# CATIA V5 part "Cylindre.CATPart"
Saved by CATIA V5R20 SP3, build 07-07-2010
Part number: Cylindre
Bounding box of the stored display mesh (mm): x -34.49 to 34.49, y -34.387 to 34.387, z -147 to -6
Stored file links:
  F:\Travaux\Modélisations\CFAO_2011\MMS\MMS_GR1\AA_OK\bmadec\Catia\Cylindre.CATPart
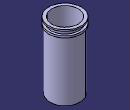
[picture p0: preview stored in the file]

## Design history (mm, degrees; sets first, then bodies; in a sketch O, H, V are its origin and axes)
Body1 (main body)
  Sketch1 on yz-plane, origin (0, 0, 0), H (0, 1, 0), V (0, 0, 1)
    line L1 (34.5, -6) -> (34.5, -21)
    line L2 (34.5, -21) -> (31.5, -21)
    line L3 (31.5, -21) -> (31.5, -147)
    line L4 (31.5, -147) -> (24.75, -147)
    line L5 (24.75, -147) -> (24.75, -123)
    line L6 (24.75, -123) -> (28, -123)
    line L7 (28, -123) -> (28, -6)
    line L8 (28, -6) -> (34.5, -6)
    distance L1 V = 34.5
    distance L3 V = 31.5
    distance L5 V = 24.75
    length L5 = 24
    length L1 = 15
    distance L8 L4 = 141
    distance L8 H = 6
    distance V L7 = 28
    vertical: L1 V, L3 V, L5 V, L7 V
    horizontal: L2 H, L4 H, L6 H, L8 H
  Shaft1: profile Sketch1, axis Sketch1.V, angle 360
  Sketch2 on yz-plane, origin (0, 0, 0), H (0, 1, 0), V (0, 0, 1)
    line L1 (35.9718, -9) -> (30, -9)
    line L2 (30, -9) -> (30, -17)
    line L3 (30, -17) -> (35.9718, -17)
    line L4 (35.9718, -17) -> (35.9718, -9)
    distance L1 H = 9
    length L2 = 8
    distance L2 V = 30
    horizontal: L1 H, L3 H
    vertical: L2 V, L4 V
  Groove1: profile Sketch2, axis Sketch2.V, angle 360
  Sketch3 on yz-plane, origin (0, 0, 0), H (0, 1, 0), V (0, 0, 1)
    line L1 (16.9243, -127) -> (29, -127)
    line L2 (29, -127) -> (29, -142)
    line L3 (29, -142) -> (16.9243, -142)
    line L4 (16.9243, -142) -> (16.9243, -127)
    reference projected line E1 (-31.5, -147) -> (31.5, -147) from edge [face of Shaft1 from Sketch1.L4 | face of Shaft1 from Sketch1.L3]
    reference projected line E2 through (0, 0) direction (0, 1) from axis of face of Shaft1 from Sketch1.L3
    distance L3 E1 = 5
    distance L2 E2 = 29
    length L2 = 15
    horizontal: L1 H, L3 H
    vertical: L2 V, L4 V
  Groove2: profile Sketch3, axis axis of face of Shaft1 from Sketch1.L3, angle 360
